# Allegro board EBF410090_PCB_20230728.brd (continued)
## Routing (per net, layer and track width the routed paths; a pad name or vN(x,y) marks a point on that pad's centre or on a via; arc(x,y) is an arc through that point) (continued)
PCIE20_RXN: length 90.5
  TOP w0.179: J24.23 104,70.1 103.79,69.89 103.79,66.76 102.95,65.91 90.05,65.91 89.61,65.47 89.61,57.29 88.65,56.34 68.55,56.34 67.48,57.4 32.56,57.4 32.07,57.89 32.07,60.93 32.01,60.98 J30.187
PCIE20_RXP: length 90.5
  TOP w0.179: J30.185 32.51,60.98 32.45,60.93 32.45,58.05 32.72,57.78 33.58,57.78 arc(33.68,57.82) 33.72,57.92 arc(33.76,58.02) 33.86,58.06 34.3,58.06 arc(34.4,58.02) 34.44,57.92 arc(34.48,57.82) 34.58,57.78 35.01,57.78 arc(35.11,57.82) 35.15,57.92 arc(35.19,58.02) 35.29,58.06 35.72,58.06 arc(35.82,58.02) 35.86,57.92 arc(35.91,57.82) 36,57.78 36.44,57.78 arc(36.54,57.82) 36.58,57.92 arc(36.62,58.02) 36.72,58.06 37.15,58.06 arc(37.25,58.02) 37.29,57.92 arc(37.33,57.82) 37.43,57.78 37.87,57.78 arc(37.97,57.82) 38.01,57.92 arc(38.05,58.02) 38.15,58.06 38.58,58.06 arc(38.68,58.02) 38.72,57.92 arc(38.76,57.82) 38.86,57.78 67.64,57.78 68.71,56.72 88.49,56.72 89.23,57.45 89.23,65.63 89.89,66.29 102.79,66.29 103.41,66.92 103.41,69.89 103.2,70.1 J24.25
PCIE20_TXN: length 72.7
  TOP w0.179: C179.1 v1(88.14,57.48) ; v1(87.34,55.27) 87.04,54.96 81.56,54.96 80.72,55.8 67.92,55.8 67.16,56.56 43.47,56.56 arc(43.37,56.61) 43.33,56.7 arc(43.29,56.8) 43.19,56.84 42.75,56.84 arc(42.65,56.8) 42.61,56.7 arc(42.57,56.61) 42.47,56.56 42.04,56.56 arc(41.94,56.61) 41.9,56.7 arc(41.86,56.8) 41.76,56.84 41.33,56.84 arc(41.23,56.8) 41.19,56.7 arc(41.14,56.61) 41.05,56.56 40.61,56.56 arc(40.51,56.61) 40.47,56.7 arc(40.43,56.8) 40.33,56.84 39.9,56.84 arc(39.8,56.8) 39.76,56.7 arc(39.72,56.61) 39.62,56.56 39.18,56.56 arc(39.08,56.61) 39.04,56.7 arc(39,56.8) 38.9,56.84 38.47,56.84 arc(38.37,56.8) 38.33,56.7 arc(38.29,56.61) 38.19,56.56 37.75,56.56 arc(37.66,56.61) 37.61,56.7 arc(37.57,56.8) 37.47,56.84 37.04,56.84 arc(36.94,56.8) 36.9,56.7 arc(36.86,56.61) 36.76,56.56 36.33,56.56 arc(36.23,56.61) 36.19,56.7 arc(36.14,56.8) 36.05,56.84 35.61,56.84 arc(35.51,56.8) 35.47,56.7 arc(35.43,56.61) 35.33,56.56 34.9,56.56 arc(34.8,56.61) 34.76,56.7 arc(34.72,56.8) 34.62,56.84 34.18,56.84 arc(34.08,56.8) 34.04,56.7 arc(34,56.61) 33.9,56.56 33.47,56.56 arc(33.37,56.61) 33.33,56.7 arc(33.29,56.8) 33.19,56.84 32.75,56.84 arc(32.66,56.8) 32.61,56.7 arc(32.57,56.61) 32.47,56.56 32.08,56.56 31.45,57.19 31.45,60.93 31.51,60.98 J30.189
  BOTTOM w0.179: v1(88.14,57.48) 87.82,57.8 87.82,58.27 88,58.44 88.85,58.44 89.2,58.09 89.2,55.32 88.85,54.96 87.64,54.96 v1(87.34,55.27)
PCIE20_TXP: length 72.7
  TOP w0.179: v1(87.34,54.28) 87.04,54.58 81.4,54.58 80.56,55.42 67.76,55.42 67,56.18 31.92,56.18 31.07,57.03 31.07,60.93 31.01,60.98 J30.191 ; C180.1 v1(87.12,57.48)
  BOTTOM w0.179: v1(87.34,54.28) 87.64,54.58 89.01,54.58 89.59,55.16 89.59,58.25 89.01,58.83 87.84,58.83 87.44,58.42 87.44,57.8 v1(87.12,57.48)
PCIE20_WAKEN_M0: length 113.3
  TOP w0.156: J30.171 v1(36.01,63.75)
  ART03 w0.142: v1(88.17,87.39) 87.69,86.91 86.26,86.91 85.67,87.5 55.24,87.5 54.03,86.28 54.03,75.23 52.83,74.04 52.83,70.89 50.9,68.96 45.69,68.96 42.14,65.4 37.66,65.4 v1(36.01,63.75)
  ART04 w0.142: v1(114.8,72.77) 113.84,73.74 104.52,73.74 104.04,74.22 104.04,85.72 103.4,86.36 89.2,86.36 v1(88.17,87.39)
  BOTTOM w0.156: R209.1 114.62,72.59 v1(114.8,72.77)
PCIE_PWREN_EN: length 86.2
  TOP w0.156: J30.149 v1(41.51,60.78)
  ART03 w0.142: v1(41.51,60.78) 41,60.27 41,59.31 41.2,59.1 44.73,59.1 45.26,58.57 45.26,44.75 48.87,41.15 55.12,41.15 55.37,40.89 57.63,40.89 59.59,42.85 65.28,42.85 66.29,43.86 71.42,43.86 74.93,47.37 87.5,47.37 89.43,49.3 102.59,49.3 v1(103.5,48.39)
  BOTTOM w0.156: v1(103.5,48.39) 103.57,48.32 R206.1
PE_TXN: length 23.6
  TOP w0.179: J24.31 100.8,70.1 100.59,69.9 100.59,68.81 99.98,68.2 89.79,68.2 88.52,66.93 88.52,61.72 87.82,61.02 87.82,59.95 88.14,59.64 C179.2
PE_TXP: length 23.6
  TOP w0.179: C180.2 87.12,59.64 87.44,59.95 87.44,61.18 88.14,61.88 88.14,67.09 89.63,68.58 99.82,68.58 100.21,68.97 100.21,69.9 100,70.1 J24.33
PHY1_LED1: length 86.1
  ART04 w0.203: J14.14 67.27,85.99 66.55,85.27 66.55,76.73 66.88,76.4 66.88,68.15 65.53,66.8 51.89,66.8 50.98,65.89 50.98,54.69 49.78,53.49 49.78,39.5 51.69,37.59 59.94,37.59 61.09,38.73 63.53,38.73 63.73,38.94 63.73,40.36 63.93,40.56 64.76,40.56 v1(65.28,40.04)
  BOTTOM w0.156: R116.1 v1(65.28,40.04) 64.81,40.51 64.39,40.51 63.86,41.04 U16.33
PHY1_LED2: length 103.3
  ART04 w0.203: v1(64.26,40.04) 64.26,38.3 64.06,38.1 62.61,38.1 62.23,37.72 62.23,37.08 61.98,36.83 51.05,36.83 48.84,39.04 48.84,54.3 49.28,54.74 49.28,55.93 49.99,56.64 49.99,66.67 50.88,67.56 64.8,67.56 65.76,68.53 65.76,87.2 66.55,87.98 80.4,87.98 J14.11
  BOTTOM w0.156: U16.34 63.46,40.84 v1(64.26,40.04) R117.1
PHY_CLKOUT125: length 2.8
  TOP w0.156: v1(63.15,40.04) 63.11,40.08 R113.2
  BOTTOM w0.156: U16.35 63.06,40.13 v1(63.15,40.04)
PWM2_M0: length 22.2
  TOP w0.156: J30.159 39.01,63.73 38.61,64.13 36.63,64.13 v1(35.01,65.75)
  ART03 w0.142: v1(35.01,65.75) 34.58,66.18 30.77,66.18 29.11,64.51 v1(25.13,64.51)
  BOTTOM w0.156: v1(25.13,64.51) 25.03,64.41 25.03,60.31 24.8,60.08 R17.1
PWM3_IR: length 141.5
  TOP w0.156: v1(37.51,60.78) 37.51,60.78 J30.165 ; v1(45.42,13.66) 45.42,17.07 42.85,19.63 42.85,50.99 v1(42.26,51.58)
  ART03 w0.142: v1(37.51,60.78) 37.03,60.31 37.03,57.55 37.34,57.25 42.19,57.25 42.69,56.75 42.69,52.01 v1(42.26,51.58) ; v1(127.38,13.21) 126.62,13.97 121.03,13.97 119.25,12.19 85.09,12.19 84.58,12.7 72.52,12.7 70.99,14.22 45.97,14.22 v1(45.42,13.66)
  BOTTOM w0.156: R46.1 C64.1 v1(127.38,13.21)
PWR_3V3_EN: length 84.8
  TOP w0.156: v1(74.68,32.46) 75.06,32.84 75.06,37.72 73.41,39.37 73.41,48.39 71.76,50.03 J30.36
  ART03 w0.142: v1(74.68,32.46) 64.97,32.46 63.7,33.73 28.37,33.73 27.09,35.01 v1(14.98,35.01)
  BOTTOM w0.156: R31.1 v1(14.98,35.01)
PWR_5V_EN: length 63.4
  TOP w0.156: J30.140 45.76,31.17 v1(45.69,31.1)
  ART03 w0.142: v1(15.98,32.95) 16.02,32.99 32.91,32.99 33.2,32.71 33.2,30.33 33.48,30.05 40.36,30.05 41.89,31.58 45.21,31.58 v1(45.69,31.1)
  BOTTOM w0.156: R33.1 14.98,38.74 15.54,38.18 15.54,33.39 v1(15.98,32.95)
PWR_12V_EN: length 47
  TOP w0.156: J30.147 42.01,64.64 v1(42.27,64.9)
  ART03 w0.142: v1(35.86,40.13) 21.81,40.13 v1(21.58,40.36)
  BOTTOM w0.156: v1(35.86,40.13) 35.86,47.22 36.4,47.75 39.17,47.75 39.47,48.06 39.47,57.68 41,59.21 41,61.44 42.27,62.71 v1(42.27,64.9) ; R29.1 v1(21.58,40.36)
PWRON_KEY: length 37.8
  TOP w0.156: J30.235 20.01,63.95 20.32,64.26 20.32,65.01 v1(19.81,65.51) ; SW1.4 SW1.3 2.04,76.26 Z1.2 C60.1 v1(1.27,73.53)
  ART03 w0.142: v1(1.27,73.53) 19.46,73.53 19.79,73.2 19.79,65.54 v1(19.81,65.51)
RECOVERY: length 52.6
  TOP w0.156: R43.2 4.19,55.07 3.86,54.74 1.65,54.74 1.3,54.38 1.3,44.96 1.65,44.6 3.73,44.6 v1(4.69,43.63) ; v1(28.56,43.16) 28.56,50.61 28.26,50.91 J30.202
  ART03 w0.142: v1(28.56,43.16) 28.08,43.64 27.15,43.64 26.7,43.18 8.13,43.18 7.68,43.63 v1(4.69,43.63)
RESET_KEY: length 37.8
  TOP w0.156: SW2.3 SW2.4 2.11,72.64 2.34,72.87 3.41,72.87 Z4.2 C61.1 4.07,74.96 4.39,75.28 v1(4.8,75.28) ; v1(20.81,64.51) 20.81,64.07 20.51,63.77 J30.233
  ART03 w0.142: v1(20.81,64.51) 20.33,64.99 20.33,73.53 19.7,74.17 16.38,74.17 15.27,75.28 v1(4.8,75.28)
RS485_1_A: length 34.2
  TOP w0.254: J10.1 68.33,17.4 66.04,19.68 58.7,19.68 58.04,20.34 58.04,21.46 v1(57.75,21.75)
  BOTTOM w0.156: R71.2 65.05,28.76
  BOTTOM w0.254: v1(57.75,21.75) R80.1 D23.2 56.42,26.04 56.83,26.45 65.1,26.45 65.51,26.86 65.51,27.43 65.05,27.88 U14.6 65.05,28.76
RS485_1_B: length 29.1
  TOP w0.254: v1(58.75,21.75) 58.45,21.45 58.45,20.6 58.95,20.09 66.21,20.09 68.14,18.16 R73.1
  BOTTOM w0.156: R76.1 66.32,28.76
  BOTTOM w0.254: v1(58.75,21.75) R79.1 D21.2 60.23,25.63 60.64,26.03 65.19,26.03 65.2,26.04 65.27,26.04 65.91,26.69 65.91,27.41 66.32,27.82 U14.7 66.32,28.76
RS485_2_A: length 37.2
  TOP w0.254: v1(44.41,21.75) 44.7,21.46 44.7,20.28 45.7,19.28 54.25,19.28 55.91,17.63 58.67,17.63 59.18,17.12 J11.1
  BOTTOM w0.156: R72.2 50.96,28.76
  BOTTOM w0.254: v1(44.41,21.75) R82.1 D24.2 43.08,25.46 43.94,26.32 51,26.32 51.41,26.73 51.41,27.3 50.96,27.76 U15.6 50.96,28.76
RS485_2_B: length 32.7
  TOP w0.254: v1(45.41,21.75) 45.11,21.45 45.11,20.45 45.87,19.68 54.42,19.68 56.07,18.03 59.52,18.03 R74.1
  BOTTOM w0.156: R78.1 52.23,28.76
  BOTTOM w0.254: v1(45.41,21.75) R81.1 D22.2 46.89,25.43 47.37,25.91 51.09,25.91 51.1,25.92 51.17,25.92 51.82,26.56 51.82,27.28 52.23,27.69 U15.7 52.23,28.76
RX8010_NIRQ1: length 165.8
  TOP w0.156: J30.20 75.76,51.11 77.98,48.89 83.16,48.89 83.44,48.61 83.44,43.69 81.31,41.55 81.31,29.49 v1(80.52,28.7)
  ART03 w0.142: v1(80.52,28.7) 76.33,28.7 73.03,25.4 50.16,25.4 49.12,24.36 19.71,24.36 17.37,26.69 2.02,26.69 1.73,26.98 1.73,59.01 2.31,59.59 2.31,62.13 2.72,62.53 2.72,71.65 3.1,72.03 5.61,72.03 v1(6.22,72.64)
  BOTTOM w0.156: v1(6.22,72.64) 7.11,73.53 U12.7
RX8010_NIRQ2: length 168.4
  TOP w0.156: J30.18 76.26,51.3 78.28,49.27 83.31,49.27 83.85,48.74 83.85,43.34 81.92,41.4 81.92,28.93 v1(81.68,28.7)
  ART03 w0.142: v1(81.68,28.7) 81.21,28.22 76.48,28.22 73.2,24.94 50.6,24.94 49.56,23.9 19.52,23.9 17.18,26.24 1.64,26.24 1.3,26.59 1.3,67.51 1.99,68.21 1.99,70.03 v1(1.57,70.46)
  BOTTOM w0.156: v1(1.57,70.46) 1.9,70.79 4.29,70.79 4.7,71.2 4.7,74.29 4.19,74.8 U12.3
RXD1_232: length 23
  ART03 w0.142: v1(20.83,26.41) 21.25,26.84 35.35,26.84 v1(35.84,26.35)
  BOTTOM w0.156: U13.13 36.45,26.96 v1(35.84,26.35)
  BOTTOM w0.254: v1(20.83,26.41) D9.2 R58.1
RXD2_232: length 8.8
  BOTTOM w0.254: U13.8 31.37,25.34 30.93,25.78 28.83,25.78 28.45,25.4 D8.2 R56.1
SARADC_VIN1: length 41.5
  TOP w0.156: v1(4.69,42.63) 5.18,43.12 5.18,43.97 4.19,44.96 R232.2 ; v1(28.56,42.16) 29.06,42.66 29.06,50.82 28.76,51.12 J30.200
  ART03 w0.142: v1(4.69,42.63) 5.12,42.2 10.58,42.2 11.05,42.67 28.05,42.67 v1(28.56,42.16)
SDMMC0_CLK: length 109.6
  TOP w0.156: J30.178 34.26,52.08 v1(33.76,51.58)
  ART03 w0.142: v1(33.76,51.58) 35.66,49.68 35.66,44.63 45.69,34.6 64.13,34.6 64.36,34.37 72.02,34.37 72.19,34.53 72.19,34.84 72.36,35 72.59,35 72.76,34.84 72.76,34.53 72.93,34.37 73.16,34.37 73.33,34.53 73.33,34.84 73.5,35 73.73,35 73.9,34.84 73.9,34.53 74.07,34.37 96.06,34.37 97.2,33.23 113.79,33.23 114.19,32.83 v1(114.19,28.7)
  BOTTOM w0.156: R63.1 113.19,27.56 113.03,27.71 113.03,30.98 113.19,31.14 114.02,31.14 114.19,30.97 v1(114.19,28.7)
SDMMC0_CMD: length 108.4
  TOP w0.156: J30.176 v1(34.76,52.58)
  ART03 w0.142: v1(34.76,52.58) 35.26,53.08 37.99,53.08 38.25,52.83 38.25,51.05 38.79,50.52 38.79,45.01 46.93,36.86 59.37,36.86 60.99,38.48 85.22,38.48 86.99,36.71 109.03,36.71 110.26,35.48 115.72,35.48 116.61,34.59 116.61,25.3 116.33,25.02 v1(115.19,25.02)
  BOTTOM w0.156: R62.1 v1(115.19,25.02)
SDMMC0_D0: length 108.9
  TOP w0.156: J30.174 35.26,52.08 v1(34.76,51.58)
  ART03 w0.142: v1(34.76,51.58) 36.14,50.2 36.14,44.82 45.94,35.03 63.25,35.03 63.55,35.33 63.55,35.89 63.73,36.07 64.16,36.07 64.33,35.9 64.33,35.42 64.49,35.25 64.73,35.25 64.9,35.42 64.9,35.9 65.06,36.07 65.3,36.07 65.47,35.9 65.47,35.42 65.63,35.25 65.87,35.25 66.04,35.42 66.04,35.9 66.2,36.07 75.39,36.07 75.56,35.9 75.56,35.65 75.72,35.48 75.96,35.48 76.13,35.65 76.13,35.9 76.29,36.07 76.6,36.07 76.74,35.92 76.74,35.67 76.91,35.5 77.14,35.5 77.31,35.67 77.31,35.93 77.48,36.09 77.71,36.09 77.88,35.93 77.88,35.67 78.05,35.5 78.28,35.5 78.45,35.67 78.45,35.93 78.62,36.09 78.85,36.09 79.02,35.93 79.02,35.67 79.19,35.5 79.42,35.5 79.59,35.67 79.59,35.93 79.76,36.09 79.99,36.09 80.16,35.93 80.16,35.67 80.33,35.5 80.56,35.5 80.73,35.67 80.73,35.93 80.9,36.09 81.13,36.09 81.3,35.93 81.3,35.67 81.47,35.5 81.7,35.5 81.87,35.67 81.87,35.93 82.04,36.09 82.27,36.09 82.44,35.93 82.44,35.67 82.61,35.5 82.84,35.5 83.01,35.67 83.01,35.93 83.18,36.09 83.41,36.09 83.58,35.93 83.58,35.67 83.75,35.5 83.98,35.5 84.15,35.67 84.15,35.92 84.29,36.07 84.71,36.07 85.95,34.82 96.37,34.82 97.54,33.65 114.15,33.65 114.63,33.17 114.63,28.98 114.91,28.7 v1(115.19,28.7)
  BOTTOM w0.156: R64.1 v1(115.19,28.7)
SDMMC0_D1: length 110.4
  TOP w0.156: J30.172 v1(35.76,52.58)
  ART03 w0.142: v1(115.19,29.84) 115.73,30.38 115.73,33.68 114.78,34.62 104.81,34.62 104.65,34.79 104.65,35.68 104.48,35.84 104.24,35.84 104.08,35.68 104.08,34.79 103.91,34.62 103.67,34.62 103.51,34.79 103.51,35.68 103.34,35.84 103.1,35.84 102.94,35.68 102.94,34.79 102.77,34.62 102.53,34.62 102.37,34.79 102.37,35.68 102.2,35.84 101.96,35.84 101.8,35.68 101.8,34.79 101.63,34.62 101.39,34.62 101.23,34.79 101.23,35.68 101.06,35.84 100.82,35.84 100.66,35.68 100.66,34.79 100.49,34.62 100.25,34.62 100.09,34.79 100.09,35.68 99.92,35.84 99.68,35.84 99.52,35.68 99.52,34.79 99.35,34.62 98.22,34.62 97,35.84 86.28,35.84 85.17,36.96 77.44,36.96 77.28,37.12 77.28,37.3 77.11,37.46 76.87,37.46 76.71,37.3 76.71,37.12 76.54,36.96 76.3,36.96 76.14,37.12 76.14,37.3 75.97,37.46 75.73,37.46 75.57,37.3 75.57,37.12 75.4,36.96 62.87,36.96 61.9,36 46.42,36 37.27,45.14 37.27,51.84 37,52.11 36.99,52.11 36.24,52.11 v1(35.76,52.58)
  BOTTOM w0.156: R65.1 v1(115.19,29.84)
SDMMC0_D2: length 108.9
  TOP w0.156: J30.170 36.26,52.08 v1(35.76,51.58)
  ART03 w0.142: v1(114.19,23.87) 113.67,24.4 113.67,32.41 113.33,32.74 96.8,32.74 95.61,33.93 64.11,33.93 63.87,34.17 45.41,34.17 35.12,44.46 35.12,49.21 33.12,51.21 33.12,51.81 33.41,52.09 35.25,52.09 v1(35.76,51.58)
  BOTTOM w0.156: R60.1 114.45,22.73 114.19,23 v1(114.19,23.87)
SDMMC0_D3: length 109.8
  TOP w0.156: J30.168 v1(36.76,52.58)
  ART03 w0.142: v1(36.76,52.58) 37.13,52.58 37.69,52.02 37.69,45.32 46.59,36.42 61.57,36.42 63.04,37.89 85.02,37.89 86.64,36.27 105.18,36.27 105.36,36.09 105.36,35.3 105.6,35.05 107.08,35.05 107.25,35.22 107.25,35.85 107.41,36.02 107.65,36.02 107.82,35.85 107.82,35.22 107.98,35.05 108.22,35.05 108.39,35.22 108.39,35.85 108.55,36.02 108.79,36.02 108.96,35.85 108.96,35.22 109.12,35.05 115.32,35.05 116.15,34.21 116.15,26.09 115.87,25.81 114.82,25.81 114.58,25.56 114.58,24.48 v1(115.19,23.87)
  BOTTOM w0.156: R61.1 v1(115.19,23.87)
SDMMC0_DET_L: length 96.5
  TOP w0.156: v1(36.76,51.58) 37.26,52.08 J30.166
  ART03 w0.142: v1(115.19,30.99) 115.19,33.35 114.43,34.11 97.97,34.11 96.72,35.36 86.1,35.36 84.93,36.53 63.35,36.53 62.34,35.51 46.17,35.51 36.76,44.92 v1(36.76,51.58)
  BOTTOM w0.156: R66.1 v1(115.19,30.99)
SIM_CLK0: length 34.7
  TOP w0.156: v1(116.12,35.99) 116.12,35.47 115.77,35.13 112.78,35.13 112.47,35.44 112.47,43.41 109.78,46.1 109.78,59.05 111.6,60.88 J24.12
  BOTTOM w0.156: v1(116.12,35.99) 115.95,35.82 R202.1
SIM_DATA0: length 29.9
  TOP w0.156: v1(113.12,35.99) 113.12,44.08 110.31,46.89 110.31,58.93 112.4,61.02 J24.10
  BOTTOM w0.156: v1(113.12,35.99) 112.9,35.78 R204.1
SIM_RST0: length 33.4
  TOP w0.156: v1(111.73,37.16) 111.76,37.18 111.76,43.1 109.27,45.59 109.27,59.28 110.8,60.81 J24.14
  BOTTOM w0.156: v1(111.73,37.16) 111.73,32.75 112.35,32.13 R201.1
SIM_VDD: length 51.5
  TOP w0.305: J24.8 113.2,60.98 111,58.77 111,47.4 114.12,44.27 v1(114.12,35.99)
  ART04 w0.381: v1(119.37,31.72) 119.37,33.13 118.67,33.83 114.73,33.83 114.12,34.44 v1(114.12,35.99)
  BOTTOM w0.305: v1(114.12,35.99) 113.92,35.79 R200.1 ; v1(119.37,31.72) 119.37,31.72 U38.1 119.96,32.37 120.27,32.68 120.27,34.92 119.15,36.04 119.15,39.67 119.74,40.26 U37.1
SPKN_OUT: length 35.4
  TOP w0.254: J30.236 19.76,57.22 v1(20.32,57.78)
  BOTTOM w0.156: 30.49,69.98 R224.1
  BOTTOM w0.254: 30.49,69.98 Z13.2 30.2,68.67 30.2,64.05 31.57,62.68 31.57,54.92 29.79,53.14 24.16,53.14 22.78,54.52 22.78,57.23 21.95,58.06 20.6,58.06 v1(20.32,57.78)
SPKP_OUT: length 36
  TOP w0.254: v1(20.32,58.78) 19.26,57.72 J30.238
  BOTTOM w0.156: 29.46,69.98 R223.1
  BOTTOM w0.254: 29.46,69.98 Z11.2 29.79,68.62 29.79,63.88 31.14,62.53 31.14,55.07 29.62,53.54 24.33,53.54 23.19,54.69 23.19,57.39 22.12,58.47 20.63,58.47 v1(20.32,58.78)
SS_TXN: length 8.7
  BOTTOM w0.158: J15.8 96.29,78.87 96.45,79.03 96.45,79.31 95.82,79.94 95.82,83.84 95.75,83.91 U19.2 U19.9 95.75,86.32 C114.1
SS_TXP: length 9.5
  BOTTOM w0.158: C115.1 96.25,86.22 U19.10 U19.1 96.25,83.91 96.18,83.84 96.18,83.56 arc(96.23,83.44) 96.35,83.39 arc(96.47,83.34) 96.52,83.22 96.52,82.92 arc(96.47,82.8) 96.35,82.75 arc(96.23,82.7) 96.18,82.58 96.18,82.29 arc(96.23,82.17) 96.35,82.12 arc(96.47,82.07) 96.52,81.95 96.52,81.66 arc(96.47,81.54) 96.35,81.49 arc(96.23,81.44) 96.18,81.32 96.18,80.09 96.81,79.46 96.81,79.08 97.02,78.87 J15.9
TXD1_232: length 34.6
  ART03 w0.142: v1(18.83,26.41) 19.41,25.83 37.32,25.83 v1(37.84,26.35)
  BOTTOM w0.156: v1(37.84,26.35) 37.71,26.48 U13.14
  BOTTOM w0.254: R59.1 D11.2 10.79,25.91 11.3,26.41 v1(18.83,26.41)
TXD2_232: length 16.3
  BOTTOM w0.254: R57.1 D10.2 24.64,26.67 25.02,27.05 32,27.05 32.63,26.42 U13.7
UART1_DIR: length 73.6
  TOP w0.156: v1(35.91,19.94) 36.33,20.35 36.33,30.32 32.76,33.89 J30.184
  ART03 w0.142: v1(35.91,19.94) 36.57,19.28 37.49,19.28 38.35,20.14 63.84,20.14 v1(65.41,21.71)
  BOTTOM w0.156: U14.3 65.05,24.93 65.37,25.24 66.01,25.24 66.32,24.93 U14.2 R75.1 v1(65.41,21.71)
UART1_RX_M0: length 82.4
  TOP w0.156: J30.194 30.26,20.27 30.39,20.14 30.39,19.42 v1(29.91,18.94)
  ART03 w0.142: v1(29.91,18.94) 29.36,19.48 29.36,22.83 30,23.47 66.75,23.47 v1(68.51,21.71)
  BOTTOM w0.156: U14.1 R69.2 v1(68.51,21.71)
UART1_TX_M0: length 73.3
  TOP w0.156: J30.196 29.76,20.09 v1(29.91,19.94)
  ART03 w0.142: v1(29.91,19.94) 29.91,22.49 30.53,23.11 61.46,23.11 v1(62.87,21.71)
  BOTTOM w0.156: v1(62.87,21.71) R67.2 U14.4
UART2_RX_M0_DEBUG: length 63.6
  TOP w0.156: v1(39.76,35.16) 40.31,35.71 40.31,50.37 39.76,50.92 J30.156
  ART03 w0.142: v1(39.76,35.16) 39.28,35.64 27.86,35.64 27.61,35.89 18.54,35.89 18.16,35.51 5.19,35.51 4.69,35.01 v1(4.69,34.01)
  BOTTOM w0.156: U10.4 4.1,29.35 3.95,29.5 R42.2 3.95,33.26 v1(4.69,34.01)
UART2_TX_M0_DEBUG: length 78.7
  TOP w0.156: v1(8.25,20.69) 7.21,21.73 7.21,35.75 6.8,36.17 5.35,36.17 v1(4.69,36.82) ; J30.158 39.26,50.65 39.76,50.15 v1(39.76,36.16)
  ART03 w0.142: v1(4.69,36.82) 5.3,36.22 15.67,36.22 16.33,36.87 39.04,36.87 v1(39.76,36.16)
  BOTTOM w0.156: v1(8.25,20.69) U9.2 5.37,20.69 5.08,20.4 5.08,18.95 5.37,18.66 R39.2
UART3_RX_M1: length 71.7
  TOP w0.156: v1(72.56,29.56) 71.37,30.75 71.37,33.65 70.46,34.57 70.46,37.82 68.45,39.83 68.45,44.32 67.76,45.01 J30.52
  ART03 w0.142: v1(31.37,30.61) 31.37,29.27 31.66,28.99 71.99,28.99 v1(72.56,29.56)
  BOTTOM w0.156: R52.2 31.37,31.37 v1(31.37,30.61) U13.9
UART3_TX_M1: length 68.3
  TOP w0.156: v1(71.56,29.56) 70.1,31.02 70.1,33.4 69.47,34.03 69.47,37.84 67.94,39.37 67.94,43.81 67.26,44.5 J30.54
  ART03 w0.142: v1(32.63,30.61) 32.63,30 33.08,29.56 v1(71.56,29.56)
  BOTTOM w0.156: U13.10 v1(32.63,30.61) 32.64,30.61 R53.2
UART4_RX_M1: length 66.4
  TOP w0.156: J30.48 68.76,45.92 69.47,45.21 69.47,40.64 72.56,37.55 v1(72.56,31.56)
  ART03 w0.142: v1(72.56,31.56) 72.4,31.39 63.14,31.39 62.61,31.93 51.66,31.93 50.79,32.8 35.62,32.8 35.17,32.35 v1(35.17,30.61)
  BOTTOM w0.156: R54.2 35.18,30.61 v1(35.17,30.61) U13.12
UART4_TX_M1: length 71.8
  TOP w0.156: J30.50 68.26,45.4 68.96,44.7 68.96,40.26 72.01,37.21 72.01,31.14 72.37,30.78 73.25,30.78 73.56,31.09 v1(73.56,31.56)
  ART03 w0.142: v1(73.56,31.56) 73.08,32.04 64.51,32.04 64.02,32.52 51.9,32.52 51.16,33.27 34.42,33.27 33.91,32.77 v1(33.91,30.61)
  BOTTOM w0.156: R55.2 33.91,30.61 v1(33.91,30.61) U13.11
UART6_DIR: length 57.9
  TOP w0.156: v1(36.91,19.94) 37.34,20.37 37.34,30.42 33.26,34.5 J30.182
  ART03 w0.142: v1(36.91,19.94) 38.13,21.16 50.81,21.16 v1(51.36,21.71)
  BOTTOM w0.156: U15.3 50.96,24.8 51.27,25.11 51.92,25.11 52.23,24.8 U15.2 R77.1 v1(51.36,21.71)
UART6_RX_M0: length 62.3
  TOP w0.156: J30.190 31.26,32.19 31.95,31.49 31.95,19.98 v1(31.91,19.94)
  ART03 w0.142: v1(54.36,21.71) 53.42,22.66 32.56,22.66 31.91,22 v1(31.91,19.94)
  BOTTOM w0.156: U15.1 R70.2 v1(54.36,21.71)
UART6_TX_M0: length 57.6
  TOP w0.156: v1(30.91,19.94) 30.76,20.09 J30.192
  ART03 w0.142: v1(48.82,21.71) 48.33,22.2 32.87,22.2 32.41,21.74 32.41,19.69 32.13,19.4 31.44,19.4 v1(30.91,19.94)
  BOTTOM w0.156: v1(48.82,21.71) R68.2 U15.4
UART7_RX_M0: length 109.3
  TOP w0.156: R225.2 v1(99.19,19.18) ; J30.186 32.26,33.27 34.47,31.06 34.47,20.38 v1(34.91,19.94)
  ART03 w0.142: v1(34.91,19.94) 35.43,19.41 35.43,18.57 35.72,18.29 82.77,18.29 83.06,18.57 83.06,22.6 83.44,22.99 98.55,22.99 99.19,22.35 v1(99.19,19.18)
UART7_TX_M0: length 109.1
  TOP w0.156: R234.2 v1(97.16,19.18) ; v1(32.91,19.94) 33.27,20.3 33.27,31.06 31.76,32.58 J30.188
  ART03 w0.142: v1(97.16,19.18) 97.16,22.19 96.87,22.48 83.91,22.48 83.63,22.19 83.63,18.1 83.31,17.78 33.91,17.78 33.4,18.29 33.4,19.45 v1(32.91,19.94)
UART9_RX_M1: length 93.4
  TOP w0.156: J30.98 56.26,50.73 55.75,50.22 55.75,34.54 56.51,33.79 56.51,29.22 57.11,28.62 70.82,28.62 74.3,25.14 74.3,18.79 75.44,17.65 v1(75.44,14.48)
  ART03 w0.142: v1(111.12,16.89) 109.41,15.18 83.51,15.18 83.19,14.86 75.82,14.86 v1(75.44,14.48)
  BOTTOM w0.156: R235.2 v1(111.12,16.89)
UART9_TX_M1: length 92.7
  TOP w0.156: v1(74.3,14.48) 74.3,17.78 73.79,18.29 73.79,25.02 70.87,27.94 56.64,27.94 56.01,28.57 56.01,33.53 55.12,34.42 55.12,50.29 55.76,50.93 J30.100
  ART03 w0.142: v1(74.3,14.48) 75.12,15.3 83,15.3 83.32,15.62 107.82,15.62 v1(109.09,16.89)
  BOTTOM w0.156: R236.2 v1(109.09,16.89)
USB2_HOST2_DM: length 43.5
  TOP w0.158: R126.1 v1(93.47,32.38) ; v1(79.01,60.78) 79.01,60.78 J30.7
  BOTTOM w0.158: v1(79.01,60.78) 79.33,60.46 83.78,60.46 84.48,59.77 84.48,58.22 86.28,56.41 86.28,53.42 87,52.7 91.19,52.7 92.39,51.5 92.39,35.66 arc(92.44,35.55) 92.55,35.5 arc(92.66,35.46) 92.71,35.34 92.71,35.03 arc(92.66,34.92) 92.55,34.87 arc(92.44,34.82) 92.39,34.71 92.39,34.4 arc(92.44,34.28) 92.55,34.24 arc(92.75,34.15) 92.84,33.95 92.84,33.89 arc(92.75,33.69) 92.55,33.6 arc(92.44,33.56) 92.39,33.44 92.39,32.37 92.72,32.05 93.15,32.05 93.47,32.37 v1(93.47,32.38)
USB2_HOST2_DP: length 43.8
  TOP w0.158: R125.1 v1(93.47,31.37) ; J30.9 78.51,60.28 v1(79.01,59.78)
  BOTTOM w0.158: v1(79.01,59.78) 79.33,60.1 83.63,60.1 84.12,59.62 84.12,58.07 85.92,56.26 85.92,53.27 86.85,52.34 91.04,52.34 92.03,51.35 92.03,32.22 92.57,31.68 93.16,31.68 v1(93.47,31.37)
USB2_HOST3_DM: length 84.4
  TOP w0.158: v1(99.54,88.38) 99.84,88.08 99.84,87.1 103.02,83.92 103.02,75.84 101.58,74.4 88.75,74.4 87.78,73.42 87.78,70.25 86.89,69.36 86.89,65.17 85.4,63.68 81.71,63.68 81.17,63.14 81.17,61.19 79.27,59.29 78.26,59.29 77.94,59.6 77.94,60.95 78.01,61.02 J30.11 ; R143.2 v1(126.49,88.39)
  ART03 w0.144: v1(99.54,88.38) 99.85,88.07 99.85,87.24 100.34,86.75 102.38,86.75 102.99,87.36 108.26,87.36 108.8,86.82 118.05,86.82 118.69,87.46 125.71,87.46 126.06,87.81 126.06,87.96 v1(126.49,88.39)
USB2_HOST3_DP: length 84.4
  TOP w0.158: R142.2 v1(125.48,88.39) ; v1(100.5,88.38) 100.2,88.08 100.2,87.25 103.38,84.07 103.38,75.69 101.73,74.04 88.9,74.04 88.14,73.27 88.14,70.1 87.25,69.21 87.25,65.02 85.55,63.32 81.86,63.32 81.53,62.99 81.53,61.04 79.42,58.93 78.11,58.93 77.58,59.46 77.58,60.95 77.51,61.02 J30.13
  ART03 w0.144: v1(125.48,88.39) 125.71,88.15 125.71,87.95 125.57,87.81 118.54,87.81 117.91,87.17 108.94,87.17 108.41,87.71 102.84,87.71 102.23,87.1 100.48,87.1 100.2,87.38 100.2,88.07 v1(100.5,88.38)
USB3_HOST1_DM: length 38.9
  TOP w0.158: J30.3 80.01,63.52 79.94,63.59 79.94,63.99 80.6,64.64 84.81,64.64 86,65.84 86,74.8 84.96,75.84 84.96,76.93 85.32,77.29 85.32,78.23 86.76,79.67 87.85,79.67 89.53,81.35 89.53,82.37 91.41,84.25 93.98,84.25 94.72,84.99 94.72,86.74 94.35,87.11 94.35,88.1 v1(94.64,88.39)
  BOTTOM w0.158: R136.2 v1(94.64,88.39)
USB3_HOST1_DP: length 38.9
  TOP w0.158: v1(93.7,88.39) 93.99,88.1 93.99,86.96 94.36,86.59 94.36,85.14 93.83,84.61 91.26,84.61 89.17,82.52 89.17,81.5 87.7,80.03 86.61,80.03 84.96,78.38 84.96,77.44 84.6,77.08 84.6,75.69 85.64,74.65 85.64,65.99 84.66,65 80.45,65 79.58,64.14 79.58,63.59 79.51,63.52 J30.5
  BOTTOM w0.158: R137.2 v1(93.7,88.39)
USB3_HOST1_SSRXN: length 99
  TOP w0.158: v1(29.01,59.78) 28.51,60.28 J30.201
  ART03 w0.144: v1(29.01,59.78) 28.69,60.11 28.13,60.11 27.64,60.6 27.64,62.35 28.36,63.06 37.93,63.06 39.02,64.15 42.33,64.15 46.14,67.97 63.68,67.97 65.9,70.2 83.9,70.2 84.79,71.08 84.79,84.71 85.74,85.67 91.98,85.67 92.27,85.95 92.27,86.51 v1(91.96,86.82)
  BOTTOM w0.158: J15.5 90.13,78.87 90.45,79.19 90.45,79.65 91.44,80.64 91.44,82.42 92.26,83.25 92.26,83.84 92.19,83.91 U18.2 U18.9 92.19,85.76 92.26,85.83 92.26,86.52 v1(91.96,86.82)
USB3_HOST1_SSRXP: length 97.3
  TOP w0.158: J30.199 v1(29.01,60.78)
  ART03 w0.144: v1(29.01,60.78) 28.69,60.46 28.28,60.46 27.99,60.74 27.99,62.2 28.5,62.71 38.07,62.71 39.17,63.8 42.47,63.8 46.29,67.62 63.82,67.62 66.05,69.85 84.05,69.85 85.13,70.93 85.13,84.56 85.89,85.32 92.13,85.32 92.62,85.81 92.62,86.51 v1(92.93,86.82)
  BOTTOM w0.158: v1(92.93,86.82) 92.62,86.52 92.62,85.83 92.69,85.76 U18.10 U18.1 92.69,83.91 92.62,83.84 92.62,83.1 91.8,82.27 91.8,80.49 90.81,79.5 90.81,79.19 91.13,78.87 J15.6
USB3_HOST1_SSTXN: length 91
  TOP w0.158: J30.197 29.51,60.28 v1(30.01,59.78)
  ART03 w0.144: v1(95.58,88.39) 95.72,88.25 95.72,86.88 94.18,85.34 94.18,82.68 93.47,81.96 91.66,81.96 90.91,81.21 90.91,79.73 90.51,79.33 90.51,78.4 90.91,78.01 90.91,76.53 90.41,76.03 90.41,75.28 89.9,74.77 86.67,74.77 85.78,73.87 85.78,70.59 84.38,69.19 69.36,69.19 68.92,68.75 66.4,68.75 64.58,66.92 46.59,66.92 42.82,63.14 39.77,63.14 38.82,62.19 29.88,62.19 29.53,61.85 29.53,60.18 29.93,59.78 v1(30.01,59.78)
  BOTTOM w0.158: C114.2 v1(95.58,88.39)
USB3_HOST1_SSTXP: length 90.3
  TOP w0.158: J30.195 v1(30.01,60.78)
  ART03 w0.144: v1(96.52,88.39) 96.22,88.39 96.07,88.25 96.07,86.74 94.53,85.2 94.53,82.53 93.62,81.62 91.8,81.62 91.25,81.07 91.25,79.59 90.86,79.19 90.86,78.55 91.25,78.15 91.25,76.39 90.75,75.89 90.75,75.13 90.04,74.42 86.82,74.42 86.12,73.73 86.12,70.44 84.52,68.84 69.5,68.84 69.06,68.4 66.55,68.4 64.72,66.57 46.74,66.57 42.96,62.8 39.91,62.8 38.96,61.85 34.78,61.85 arc(34.67,61.8) 34.63,61.7 arc(34.58,61.59) 34.48,61.54 34.21,61.54 arc(34.1,61.59) 34.05,61.7 arc(34.01,61.8) 33.9,61.85 33.63,61.85 arc(33.52,61.8) 33.48,61.7 arc(33.43,61.59) 33.33,61.54 33.06,61.54 arc(32.95,61.59) 32.9,61.7 arc(32.86,61.8) 32.75,61.85 32.48,61.85 arc(32.37,61.8) 32.33,61.7 arc(32.28,61.59) 32.18,61.54 31.91,61.54 arc(31.8,61.59) 31.75,61.7 arc(31.71,61.8) 31.6,61.85 31.33,61.85 arc(31.22,61.8) 31.18,61.7 arc(31.13,61.59) 31.03,61.54 30.76,61.54 arc(30.65,61.59) 30.6,61.7 arc(30.56,61.8) 30.45,61.85 30.02,61.85 29.88,61.7 29.88,60.91 v1(30.01,60.78)
  BOTTOM w0.158: C115.2 v1(96.52,88.39)
USB20_HOST_PWR_EN: length 115.2
  TOP w0.156: J30.28 73.76,50.32 75.69,48.39 75.69,44.32 76.67,43.35 v1(77.24,43.35)
  ART03 w0.142: v1(77.24,43.35) 77.76,43.86 78.66,43.86 79.68,44.88 87.81,44.88 89.61,46.68 114.17,46.68 115.95,48.46 v1(117.83,48.46)
  ART04 w0.142: v1(134.44,71.38) 134.2,71.14 127.46,71.14 127.18,70.86 127.18,61.19 126.89,60.91 126.09,60.91 125.81,60.62 125.81,51.61 124.54,50.34 122.58,50.34 121.26,49.02 118.39,49.02 v1(117.83,48.46)
  BOTTOM w0.156: v1(134.44,71.38) 135.13,72.07 135.13,79.09 134.75,79.48 131.88,79.48 131.52,79.83 131.52,81.36 131.24,81.63 130.06,81.63 129.74,81.95 129.74,83.1 129.43,83.41 128.99,83.41 128.7,83.7 128.7,85.42 128.4,85.72 R141.1
USB20_OTG_PWR_EN: length 56.1
  TOP w0.156: J30.138 v1(46.26,52.58)
  ART03 w0.142: v1(45.59,72.47) 21.82,72.47 21.46,72.11 21.46,66.17 v1(20.81,65.51)
  BOTTOM w0.156: v1(45.59,72.47) 45.57,72.44 45.57,66.9 46.26,66.21 v1(46.26,52.58) ; v1(20.81,65.51) 20.32,65.02 20.32,63.88 19.94,63.5 R150.1
USB30_HOST_PWR_EN: length 62.1
  TOP w0.156: J30.41 70.51,60.78
  TOP w0.305: 70.51,60.78 v1(70.51,60.78)
  BOTTOM w0.156: v1(70.51,60.78) 70.51,61.95 70.92,62.36 73.51,62.36 73.94,62.79 73.94,65.91 74.45,66.42 84.52,66.42 84.84,66.73 84.84,70.99 85.34,71.5 90.55,71.5 93.6,74.55 102.68,74.55 103.12,74.99 103.12,83.38 103.44,83.69 109.6,83.69 110.11,84.2 R147.1
USB OTG: length 55.3
  TOP w0.305: R149.1 v1(38.35,46.57)
  ART03 w0.305: v1(44.08,75.36) 38.81,75.36 37.08,77.09 32.38,77.09 30.17,79.3 v1(24.13,79.3)
  BOTTOM w0.305: v1(38.35,46.57) 41.24,46.57 41.68,47.01 41.68,56.72 44.32,59.36 44.32,75.12 v1(44.08,75.36)
  vias: v1(23.13,80.3) v1(23.13,79.3) v1(24.13,80.3)
USB_OTG0_DM: length 39.3
  TOP w0.158: J30.203 28.01,63.52 27.94,63.59 27.94,64 28.1,64.15 28.73,64.15 29.36,63.52 31.72,63.52 32.64,64.44 32.64,65.33 35.06,67.75 35.06,86.25 34.57,86.74 29.56,86.74 28.1,88.21 28.1,88.58 v1(28.45,88.94)
  BOTTOM w0.158: v1(28.45,88.94) 28.45,88.28 R134.2
USB_OTG0_DP: length 41.9
  TOP w0.158: J30.205 27.51,63.52 27.58,63.59 27.58,64.15 27.95,64.51 28.88,64.51 29.51,63.89 31.57,63.89 32.28,64.59 32.28,65.48 34.7,67.9 34.7,76.65 arc(34.65,76.77) 34.53,76.82 arc(34.41,76.87) 34.37,76.98 34.37,77.29 arc(34.41,77.4) 34.53,77.45 arc(34.65,77.5) 34.7,77.62 34.7,77.92 arc(34.65,78.04) 34.53,78.09 arc(34.41,78.13) 34.37,78.25 34.37,78.55 arc(34.41,78.67) 34.53,78.72 arc(34.65,78.77) 34.7,78.88 34.7,79.19 arc(34.65,79.3) 34.53,79.35 arc(34.41,79.4) 34.37,79.52 34.37,79.82 arc(34.41,79.94) 34.53,79.98 arc(34.65,80.03) 34.7,80.15 34.7,80.45 arc(34.65,80.57) 34.53,80.62 arc(34.41,80.67) 34.37,80.78 34.37,81.09 arc(34.41,81.2) 34.53,81.25 arc(34.65,81.3) 34.7,81.42 34.7,81.72 arc(34.65,81.83) 34.53,81.88 arc(34.41,81.93) 34.37,82.05 34.37,82.35 arc(34.41,82.47) 34.53,82.52 arc(34.65,82.56) 34.7,82.68 34.7,82.98 arc(34.65,83.1) 34.53,83.15 arc(34.41,83.2) 34.37,83.31 34.37,83.62 arc(34.41,83.73) 34.53,83.78 arc(34.65,83.83) 34.7,83.95 34.7,84.25 arc(34.65,84.37) 34.53,84.42 arc(34.41,84.46) 34.37,84.58 34.37,84.88 arc(34.41,85) 34.53,85.05 arc(34.65,85.1) 34.7,85.21 34.7,86.1 34.42,86.38 29.41,86.38 27.73,88.06 27.73,88.63 v1(27.43,88.94)
  BOTTOM w0.158: v1(27.43,88.94) 27.43,88.28 R135.2
USB_OTG0_ID: length 44.1
  TOP w0.156: J30.160 v1(38.76,52.58)
  ART03 w0.142: v1(43.08,76.38) 38.94,76.38 37.34,77.98 33.16,77.98 v1(31.52,79.62)
  BOTTOM w0.156: v1(43.08,76.38) 42.55,75.84 42.55,67.16 41.75,66.36 41.75,62.96 40.01,61.21 40.01,59.18 38.76,57.94 v1(38.76,52.58) ; v1(31.52,79.62) 31.13,80.01 R138.2
USB_OTG0_VBUSDET: length 6.3
  TOP w0.156: R149.2 38.91,48.81 38.91,50.11 R151.1 38.26,50.76 J30.162
USER_LED: length 123.1
  TOP w0.156: v1(44.69,31.1) 45.26,31.67 J30.142 ; v1(128.65,16.12) 128.65,18.59 128.33,18.91 R45.2
  ART03 w0.142: v1(44.69,31.1) 45.21,30.58 84.04,30.58 85.38,29.23 109.96,29.23 110.44,28.75 110.44,21.89 110.87,21.46 119.38,21.46 120.8,20.04 120.8,16.95 121.64,16.12 v1(128.65,16.12)
WLAN_PWR_EN: length 92.3
  TOP w0.156: R128.1 91.94,29.67 91.63,29.35 89.95,29.35 88.9,30.4 v1(88.9,49.5)
  TOP w0.179: v1(41.51,59.78) 41.01,60.28 J30.151
  ART03 w0.142: v1(41.51,59.78) 45.44,59.78 45.72,59.5 45.72,45.44 48.92,42.24 55.24,42.24 55.68,41.81 57.08,41.81 59.29,44.02 64.6,44.02 65.35,44.78 71.45,44.78 74.55,47.88 87.28,47.88 v1(88.9,49.5)
N03801: length 3.8
  BOTTOM w0.203: C8.2 R4.2 R6.1 6.17,55.81 U3.4
N15118698: length 3.7
  BOTTOM w0.156: U1.4 C4.1 R1.2
N15119063: length 1.9
  BOTTOM w0.156: R2.1 7.93,33.84 U1.3
N15122947: length 3.4
  BOTTOM w0.156: U2.4 17.34,53.79 C9.1 R3.2
N15123057: length 2
  BOTTOM w0.156: U2.3 17.34,49.01 17.14,48.82 R5.1
N15599533: length 3.3
  BOTTOM w0.156: U16.25 67.65,44.65 R96.2
N15599537: length 3.5
  BOTTOM w0.156: U16.24 67.03,45.05 R97.2
N15599541: length 4
  BOTTOM w0.156: R99.2 67.56,46.6 67.56,46.23 66.79,45.45 U16.23
N15599545: length 4.5
  BOTTOM w0.156: U16.22 66.55,45.85 67.06,46.35 67.06,46.73 67.56,47.24 67.56,47.62 R100.2
N15599549: length 3.2
  BOTTOM w0.156: R101.2 67.79,43.85 U16.27
N15599553: length 3
  BOTTOM w0.156: U16.26 68.26,44.25 R102.2
N15599792: length 7.5
  BOTTOM w0.305: R90.2 R94.1 R93.1 R91.1 73.41,43.57 73.15,43.31 R95.1
N15600759: length 3.1
  BOTTOM w0.156: R108.1 R109.1 64.26,51.55 R107.1 R106.2
N15600826: length 6.9
  BOTTOM w0.156: U16.31 64.67,41.4 64.8,41.27 65.35,41.27 66.55,40.08 R110.2 67.18,38.47 67.18,37.33 R112.2
N15601838: length 6.6
  BOTTOM w0.156: U16.37 62.27,39.78 C83.1 62.23,38.47 62.23,37.33 Y1.1
N15601846: length 8.1
  BOTTOM w0.156: U16.36 62.67,39.69 C84.1 62.54,38.4 62.54,35.78 Y1.3
N15602572: length 6.5
  BOTTOM w0.156: R118.1 65.91,37.33 65.91,40.13 65.15,40.89 64.59,40.89 64.27,41.22 U16.32
N15602600: length 2.2
  TOP w0.156: R121.2 v1(64.26,37.43) R122.1
  BOTTOM w0.156: R117.2 v1(64.26,37.43)
N15603170: length 4
  BOTTOM w0.508: C85.1 J14.1
N15605512: length 3.2
  BOTTOM w0.156: U16.39 61.46,40.94 61.4,40.87 61.4,40.86 61.21,40.68 61.21,39.74 R98.1
N15605755: length 11.7
  BOTTOM w0.203: U16.28 67.02,43.45
  BOTTOM w0.305: R89.1 R92.1 C79.1 C80.1 73.41,42.24 72.98,42.67 67.8,42.67 67.02,43.45
N15611443: length 3.4
  BOTTOM w0.156: U21.4 C118.1 R141.2
N15611553: length 1.8
  BOTTOM w0.156: R144.1 118.69,87.56 U21.3
N15653247: length 5.7
  BOTTOM w0.203: R150.2 C124.1 16.58,64.51 16.38,64.71 16.38,66.67 16.58,66.87 U25.4
N15653357: length 2.5
  BOTTOM w0.156: U25.3 18.86,66.87 18.67,66.67 18.67,65.9 R153.1
N15653957: length 3.6
  BOTTOM w0.156: U24.4 108.78,87.56 109.09,87.25 C121.1 R147.2
N15654067: length 4.2
  BOTTOM w0.156: U24.3 103.83,87.56 103.5,87.88 103.5,88.52 103.76,88.77 R148.1
N15659726: length 3.7
  TOP w0.203: R7.2 R8.1 C18.2 5.21,54.99 v1(5.33,54.86)
  BOTTOM w0.203: U3.5 v1(5.33,54.86)
N15752445: length 38.1
  TOP w0.762: U26.G3 U26.G4
  ART03 w0.762: U26.G2 58.09,84.8 59.01,85.72 63.67,85.72 64.59,84.8 U26.G4
  BOTTOM w0.762: U26.G2 58.09,70.1 ; U26.G4 64.64,82.26 L9.1
N15772454: length 3
  TOP w0.156: R162.2 128.27,49.02 128.77,48.53 J19.14
N15774097: length 12.7
  TOP w0.156: J18.14 132.65,70.62 133.55,69.72 v1(133.55,68.24)
  BOTTOM w0.156: v1(133.55,68.24) 133.03,67.73 131.99,67.73 131.83,67.56 131.83,65.28 131.32,64.77 R161.2
N15830872: length 26.6
  TOP w0.203: C190.2 v1(28.45,71.13)
  BOTTOM w0.203: v1(28.45,71.13) 28.08,71.5 Z9.2 28.08,73.27 27.07,74.28 27.07,76.4 28.01,77.34 33.93,77.34 34.22,77.34 35.18,78.3 35.18,81.61 35.79,82.22 36.83,82.22 37.24,81.81 J25.5 37.44,80.57 J25.3
N15830941: length 32.1
  TOP w0.203: C189.2 v1(26.45,71.13)
  BOTTOM w0.203: v1(26.45,71.13) 26.79,71.47 Z8.2 26.79,73.16 26.26,73.69 26.26,76.7 27.61,78.05 33.93,78.05 34.47,78.59 34.47,81.98 35.73,83.23 38.2,83.23 J25.2 43.12,84.27 R218.2
N15838979: length 6.8
  BOTTOM w0.254: R217.2 33.53,73.91 34.29,74.67 J25.4
N15851038: length 2
  TOP w0.254: R216.1 37.22,65.66 C185.1 R215.2
N15852295: length 5.5
  BOTTOM w0.254: R223.2 29.82,71.34 29.82,74.95 28.97,75.8 J29.1
N15852481: length 5.1
  BOTTOM w0.254: J29.2 30.23,75.26 30.23,71.24 R224.2
N15980269: length 2.3
  TOP w0.254: J10.2 70.52,16.34 R73.2
N16735828: length 1.9
  TOP w0.156: R45.1 LED1.1
N16735933: length 1.9
  TOP w0.156: R48.1 LED2.1
N16793147: length 6.2
  BOTTOM w0.156: J9.1 119.97,22.26 D12.2 118.91,22.15 117.54,22.15 R60.2
N16793149: length 6.1
  BOTTOM w0.156: J9.7 119.66,28.86 D16.2 118.91,28.12 117.54,28.12 R64.2
N16793151: length 6.4
  BOTTOM w0.156: R63.2 117.52,27 118.94,27 D15.2 120.4,26.66 J9.5
N16793153: length 6.2
  BOTTOM w0.156: R62.2 117.54,24.43 118.91,24.43 D14.2 120.06,24.46 J9.3
N16793155: length 6.2
  BOTTOM w0.156: J9.2 120.01,23.36 D13.2 118.94,23.32 117.52,23.32 R61.2
N16793157: length 6
  BOTTOM w0.156: J9.8 119.61,29.96 D17.2 118.94,29.29 117.52,29.29 R65.2
N16793300: length 6
  BOTTOM w0.156: J9.9 119.57,31.06 D18.2 118.94,30.43 117.52,30.43 R66.2
N16795570: length 1.9
  TOP w0.156: R49.1 LED3.1
N16795883: length 6.8
  TOP w0.156: R25.1 3.17,67.94 v1(3.43,68.2)
  TOP w0.203: R24.2 C37.2 R25.1 R23.2
  BOTTOM w0.203: U5.5 v1(3.43,68.2)
N16811933: length 3.9
  TOP w0.156: J24.1 v1(116,69.4)
  BOTTOM w0.156: v1(116,69.4) 116,69.87 R208.2 R209.2
N16823854: length 2.7
  TOP w0.156: J24.7 v1(113.6,69.4)
  BOTTOM w0.156: R210.2 v1(113.6,69.4)
N16928945: length 3.9
  TOP w0.156: R211.1 105.2,59.25 J24.20
N16929135: length 4
  TOP w0.156: R212.1 104.4,59.31 J24.22
N16980859: length 18.9
  BOTTOM w0.156: U37.2 121.58,42.8 121.26,42.49 121.26,41.13 120.95,40.82 119.3,40.82 118.67,40.18 118.67,35.76 119.37,35.06 U38.6 119.37,33.14 119.13,32.89 116.72,32.89 C178.1 R201.2
N16980861: length 18.2
  BOTTOM w0.156: R202.2 C177.1 117.54,33.72 U38.4 118.37,33.72 118.37,34.79 117.65,35.51 117.65,40.82 118.67,41.83 120.04,41.83 120.32,42.11 120.32,44.59 120.63,44.9 121.05,44.9 121.49,45.34 U37.3
N16980863: length 21.2
  BOTTOM w0.156: R204.2 R200.2 C176.1 114.94,33.53 115.26,33.2 116.14,33.2 118.65,33.2 118.87,33.42 U38.5 118.87,34.92 118.14,35.66 118.14,40.54 118.95,41.35 120.41,41.35 120.73,41.66 120.73,43.46 121.34,44.07 U37.7
N17405290: length 3.8
  BOTTOM w0.203: U5.4 2.48,68.91 R22.1 R20.2 C29.2
N17423608: length 5.9
  TOP w0.203: R14.2 R15.1 C27.2 11.94,54.61 v1(12.19,54.86)
  BOTTOM w0.203: U4.5 v1(12.19,54.86)
N17423737: length 3.9
  BOTTOM w0.203: C20.2 R11.2 R13.1 13.15,55.81 U4.4
N17430242: length 1.8
  BOTTOM w0.156: U7.3 7.8,41.59 R34.1
N17430314: length 3.8
  BOTTOM w0.156: R33.2 C47.1 U7.4
N17443353: length 1.9
  BOTTOM w0.156: R32.1 8.23,37.84 8.42,37.65 U6.3
N17443371: length 3.7
  BOTTOM w0.156: R31.2 C41.1 U6.4
N17444423: length 16.7
  BOTTOM w0.156: 20.57,43.04 R27.2
  BOTTOM w0.203: 20.57,43.04 20.57,42.42 20.34,42.19 17.36,42.19 17.11,41.93 Q6.3 ; R27.2 C38.2 20.01,45.02 Q4.1 18.57,45.59 14.61,45.59 13.98,44.96 11.96,44.96 Q5.1
N17444523: length 3.3
  BOTTOM w0.156: R29.2 R30.1 Q6.1
N17454508: length 7
  BOTTOM w0.156: U13.1 40.25,20 39.94,19.68 38.03,19.68 37.72,20 C71.2
N17454513: length 1.8
  BOTTOM w0.156: U13.3 37.72,23.49 C71.1
N17455367: length 1.8
  BOTTOM w0.156: C72.2 36.45,23.49 U13.4
N17455372: length 3.9
  BOTTOM w0.156: C72.1 35.49,20.71 35.17,21.02 U13.5
N17455499: length 1.8
  BOTTOM w0.156: C70.1 33.91,21.71 U13.6
N17455508: length 1.8
  BOTTOM w0.156: C68.1 U13.2
N17466585: length 0.9
  BOTTOM w0.203: U16.30 65.94,42.65 66.17,42.42
N17592172: length 3.9
  BOTTOM w0.156: U36.4 R205.1 R203.2 C169.2
N17592286: length 3.6
  BOTTOM w0.156: R206.2 103.57,46.08 103.36,45.87 101.85,45.87 101.47,45.49 U36.5
N17633217: length 6.1
  TOP w0.156: U22.3 124.59,77.74 C119.1 124.71,77.08 124.71,75.71 Y2.1
N17633237: length 4.3
  TOP w0.156: U22.4 125.09,77.74 C120.2 125.36,76.82 Y2.3
N17633305: length 2.3
  TOP w0.156: U22.16 124.59,86.36 R145.2
N17633317: length 2.3
  TOP w0.156: R146.2 123.59,86.35 U22.18
N17685591: length 13.1
  TOP w0.203: Q12.1 122.82,34.73 123.06,34.49 123.06,32.49 122.14,31.56 Q13.1 122.96,30.68 122.96,27.68 123.22,27.43 Q14.3 125.35,27.43 125.6,27.68 C165.2 R196.2
N17685601: length 3.1
  TOP w0.156: Q14.1 122.02,28.45 R199.1 R198.2
N17690217: length 1.3
  BOTTOM w0.156: U35.3 69.66,23.81 R195.1
N17690290: length 4.9
  BOTTOM w0.156: R193.2 C162.1 69.66,31.31 U35.4
N17695706: length 11.5
  TOP w0.156: C139.1 120.96,65.28 120.42,64.74 120.42,63.9 120.76,63.56 v1(120.83,63.56) U29.4 ; v1(120.83,67.49) 120.83,68.07 121.15,68.39 U31.4
  BOTTOM w0.156: v1(120.83,67.49) 120.35,67 120.35,65.07 120.77,64.65 120.77,63.63 ; 120.77,63.63 v1(120.83,63.56) ; 120.77,63.63 R172.2
N17695791: length 3.2
  TOP w0.156: U31.3 125.21,68.39 125.5,68.1 125.5,66.98 125.68,66.8 R175.1
N17695827: length 2
  TOP w0.156: U29.3 125.36,63.56 125.53,63.73 R174.1
N17697466: length 3.9
  BOTTOM w0.508: R114.1 74.68,85.99 J14.13
N17697880: length 2
  TOP w0.156: U33.3 125.31,60.26 125.48,60.43 R182.1
N17697953: length 4.3
  TOP w0.156: R180.2 C150.1 U33.4
N17701231: length 2.4
  TOP w0.254: J11.2 61.72,17.29 61.38,17.63 R74.2
N17702194: length 9
  BOTTOM w0.254: R81.2 45.57,20.15 45.13,19.72 45.13,18.93 44.42,18.22 42.99,18.22 42.42,17.65 42.42,16.38 42.67,16.13 J12.3
N17702199: length 9
  BOTTOM w0.254: R82.2 44.32,20.15 44.72,19.75 44.72,19.1 44.25,18.63 42.82,18.63 42.01,17.82 42.01,16.36 41.79,16.13 J12.4
N17702222: length 14.4
  BOTTOM w0.254: R80.2 57.49,20.15 58,19.65 58,18.98 57.49,18.47 50.28,18.47 49.63,17.82 49.63,16.64 49.13,16.13 J12.2
N17702231: length 14.6
  BOTTOM w0.254: J12.1 50.54,16.13 50.04,16.64 50.04,17.65 50.45,18.06 57.66,18.06 58.41,18.81 58.41,19.65 58.92,20.15 R79.2
N17728858: length 1.4
  BOTTOM w0.305: D19.1 64.31,32.59 64.52,32.38 R71.1
N17729021: length 1.4
  BOTTOM w0.305: D20.1 50.22,32.59 50.43,32.38 R72.1
N17731599: length 4.7
  BOTTOM w0.254: J8.6 10.79,17.83 R59.2
N17731608: length 4.3
  BOTTOM w0.254: R58.2 20.83,16.85 J8.4
N17731627: length 5.3
  BOTTOM w0.254: R56.2 28.45,19.22 J8.1
N17748815: length 1.8
  BOTTOM w0.508: R26.2 13.61,43.12 Q5.2
N17750545: length 2.7
  BOTTOM w0.156: Q1.1 24.32,65.98 R12.2 23.37,65.03 Q2.3
N17750554: length 8.3
  BOTTOM w0.381: Q1.3 23.37,70.43 23.67,70.74 D2.1 24.13,71.67 J2.1
N17750632: length 2.9
  BOTTOM w0.156: R18.1 R17.2 24.32,61.14 Q2.1
N17770939: length 2.7
  TOP w0.158: R142.1 125.8,86.17 125.8,86.05 125.18,85.44 125.18,85.11 125.09,85.02 U22.15
N17770942: length 2.6
  TOP w0.158: R143.1 126.16,86.17 126.16,85.9 125.55,85.29 125.55,85.06 125.59,85.02 U22.14
N17861933: length 4.1
  TOP w0.381: U11.2 v1(124.22,10.29)
  BOTTOM w0.381: v1(124.22,10.29) 123.82,10.69 C65.1 C66.1 R47.1
N17863087: length 2.9
  TOP w0.156: U11.3 v1(125.49,10.29)
  BOTTOM w0.156: v1(125.49,10.29) 125.48,10.29 R44.2 R46.2
N17946485: length 9.6
  TOP w0.156: SW3.4 1.43,62.59 1.12,62.29 1.12,58.6 1.43,58.29 SW3.3 2.16,58.24 Z5.2 C63.1 R43.1
N17975561: length 8.6
  BOTTOM w0.305: J7.1 16.87,76.85 16.38,77.34 D7.2 12.69,76.33 R51.1 R50.2
N18056005: length 3.5
  TOP w0.156: R128.2 R127.2 C109.2 90.94,33.24 Q7.1
N18056634: length 11.7
  TOP w0.156: U17.2 106.28,29.34 arc(105.21,28.89) 104.77,27.82 C107.1 104.78,23.74
  TOP w0.508: C106.1 104.78,23.74
N18056637: length 2.7
  TOP w0.156: 104.78,20.69 C108.1 104.78,20.71
  TOP w0.508: CN1.1 104.78,20.69 ; C106.2 104.78,20.71
N18057325: length 4.4
  TOP w0.158: U17.7 97.9,32.37 97.58,32.06 96.03,32.06 95.7,32.38 R126.2
N18057335: length 4.1
  TOP w0.158: U17.6 97.9,31.54 97.74,31.7 96.03,31.7 95.7,31.37 R125.2
N18091011: length 1.4
  BOTTOM w0.156: D6.1 11.68,74.57 R50.1
N18111918: length 18.4
  TOP w0.156: v1(123.04,46.05) 122.8,46.29 U32.4 120.86,46.29 120.68,46.47 120.68,47.7 120.86,47.88 R171.2 ; U30.4 120.81,41.46 120.57,41.69 120.57,42.54 120.95,42.92 C136.1 123.12,42.37 124.75,42.37 v1(125.31,42.92)
  BOTTOM w0.156: v1(123.04,46.05) 124.79,46.05 125.31,45.53 v1(125.31,42.92)
N18111989: length 3.1
  TOP w0.156: R176.1 125.71,44.7 125.4,45.02 125.4,46.07 125.19,46.29 U32.3
N18112037: length 2
  TOP w0.156: U30.3 125.21,41.46 125.37,41.63 R173.1
N18115454: length 2
  TOP w0.156: R188.1 125.48,38.33 125.31,38.16 U34.3
N18115527: length 4.5
  TOP w0.156: U34.4 C153.1 R187.2
N18173560: length 25.9
  TOP w0.508: L8.1 21.08,83.7 21.59,84.21 J16.C4
  ART03 w0.508: J16.C4 23.01,86.38 23.5,86.87 31.16,86.87 31.65,86.38 J16.C3
  BOTTOM w0.508: J16.C3 J16.C1 ; J16.C4 J16.C2
N18175084: length 1.7
  BOTTOM w0.156: D26.3 27.05,80.51 R138.1
N18245213: length 26.4
  TOP w0.156: LED4.1 7.93,49.27 8.11,49.09 9.85,49.09 10.16,49.4 10.16,52.01 10.47,52.32 v1(12.26,52.32)
  ART03 w0.142: v1(12.26,52.32) 11.25,53.34 6.48,53.34 6.15,53.67 6.15,63.72 v1(6.21,63.78)
  BOTTOM w0.156: v1(6.21,63.78) 6.73,63.25 Q3.3
N18245628: length 1.5
  TOP w0.156: R16.2 LED4.2
N18246356: length 2.4
  BOTTOM w0.156: R19.2 R21.1 7.23,59.66 Q3.1
N18288623: length 8.8
  TOP w0.156: R239.1 R232.1 C192.1 Z23.2 2.09,47.94 SW4.3 SW4.4
N18341998: length 3.8
  BOTTOM w0.508: R111.1 76.96,85.99 J14.12
N18348384: length 4.3
  BOTTOM w0.254: J8.3 24.64,16.85 R57.2
N18461230: length 3.9
  BOTTOM w0.156: Q4.2 19.08,43.05
  BOTTOM w0.508: 19.08,43.05 R26.1
N18494968: length 9.7
  TOP w0.156: J34.2 90.01,12.36 D48.2 85.96,16.41 85.96,17.89 R237.1
N18494970: length 10
  TOP w0.156: R238.1 87.23,17.89 87.23,16.41 D47.2 92.01,11.63 J34.3
N18495009: length 6.5
  TOP w0.156: J32.2 78.35,11.01 D50.2 R222.1
N18495011: length 6.6
  TOP w0.156: R233.1 D49.2 79.38,11.3 J32.3
N18495097: length 9.2
  TOP w0.156: J35.2 102.01,13.44 D52.2 R234.1
N18495099: length 9.2
  TOP w0.156: J35.3 104.01,13.47 D51.2 R225.1
N18495175: length 8.9
  BOTTOM w0.156: R236.1 D54.2 110.11,14.03 110.42,13.71 113.57,13.71 114.01,13.28 J36.2
N18495177: length 9.1
  BOTTOM w0.156: R235.1 D53.2 112.14,14.61 112.15,14.6 115.57,14.6 116.01,14.16 J36.3

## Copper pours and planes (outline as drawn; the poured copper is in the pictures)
1V05_PHY on BOTTOM: 67.64,38.81 71.35,38.81 71.48,38.94 71.48,41.99 71.3,42.16 70.13,42.16 70.13,39.78 69.95,39.6 67.79,39.6 67.64,39.45
3V3_AVDD_PHY on BOTTOM: 57.73,40.31 59.72,40.31 59.87,40.16 59.87,38.81 58.93,38.81 58.72,38.61 58.72,38.33 57.91,38.33 57.91,39.45 57.73,39.62
3V3_EDP on TOP: 131.37,25.55 131.44,25.37 131.62,25.3 132.64,25.3 132.82,25.37 132.89,25.55 132.89,25.83 132.82,26.01 132.64,26.08 131.62,26.08 131.44,26.01 131.37,25.83
3V3_EDP on BOTTOM: 71.25,25.91 71.25,24.38 73.28,24.38 73.53,24.13 73.53,17.14 73.66,17.02 74.93,17.02 75.06,17.14 75.06,25.78 74.8,26.03 71.37,26.03
3V3_EDP on ART04: 130.66,25.96 132.72,25.96 133.12,25.55 133.12,15.09 132.26,14.22 79.15,14.22 78.64,13.71 78.64,11.4 78.33,11.1 57.78,11.1 57.43,11.45 57.43,17.14 57.89,17.6 129.41,17.6 130.25,18.44 130.25,25.55
3V3_IMAGE_1 on TOP: 130.63,65.48 125.15,65.48 124.43,66.19 123.72,66.19 123.72,66.8 125.2,66.8 125.73,66.27 130.63,66.27
3V3_IMAGE_2 on TOP: 130.63,43.36 124.03,43.36 123.72,43.66 123.72,44.7 124.92,44.7 124.92,44.22 125.12,44.02 129.18,44.02 129.34,44.17 130.63,44.17
5V0_CAM_1 on BOTTOM: 131.06,68.81 131.06,67.46 130.89,67.28 127.81,67.28 127.64,67.46 127.64,68.66 127.81,68.83 131.04,68.83
5V0_CAM_1 on ART03: 128.98,58.34 126.11,58.34 125.83,58.62 125.83,67.41 126.29,67.87 129.03,67.87 129.21,67.69 129.21,67.08 129.03,66.9 127.46,66.9 127.15,66.6 127.15,59.71 127.41,59.46 128.98,59.46 129.21,59.23 129.21,58.57
5V0_CAM_2 on TOP: 123.65,36.04 123.72,35.86 123.9,35.79 128.93,35.79 129.11,35.86 129.18,36.04 129.18,36.4 129.11,36.58 128.93,36.65 123.9,36.65 123.72,36.58 123.65,36.4
5V0_CAM_2 on BOTTOM: 129.79,52.04 129.79,37.46 129.39,37.06 127.86,37.06 127.61,36.8 127.61,36.12 127.86,35.86 130.4,35.86 131.09,36.55 131.09,52.04
5V0_IMAGE_1 on TOP: 130.63,65.28 130.63,61.57 130.33,61.26 123.8,61.26 123.7,61.37 123.7,61.97 125.81,61.97 125.88,62.05 129.01,62.05 129.34,62.38 129.34,65.28
5V0_IMAGE_2 on TOP: 130.66,43.18 130.66,39.45 130.33,39.11 123.83,39.11 123.7,39.24 123.7,39.85 125.81,39.85 125.91,39.95 129.03,39.95 129.34,40.26 129.34,43.18
12V_EDP on TOP: 123.47,30.15 127.76,30.15 127.99,30.38 127.99,33.91 127.81,34.09 127.03,34.09 126.85,33.91 126.85,31.49 126.44,31.09 123.47,31.09
GND on TOP (solid shape): 84.57,79.25 84.68,79.21 84.73,79.1 84.73,78.04 83.48,78.01 83.51,79.25
GND on BOTTOM (solid shape): 26.96,30.69 26.29,30.03 26.16,30 26.04,30.03 25.36,30.69 26.16,31.56
GND on TOP: 65.56,53.31 65.63,53.13 65.81,53.06 66.75,53.06 66.93,53.13 67.01,53.31 67.01,55.7 66.93,55.88 66.75,55.96 65.81,55.96 65.63,55.88 65.56,55.7
GND on TOP: 111.89,48.26 111.35,48.79 111.35,58.24 111.53,58.42 118.67,58.42 118.67,59.84 118.74,60.02 118.92,60.1 122.68,60.1 122.68,68.43 122.99,68.73 130.07,68.73 130.81,67.99 130.81,58.27 130.45,57.91 129.26,57.91 129.26,58.75 128.07,58.75 128.07,57.91 123.62,57.91 123.62,57.3 123.55,57.12 123.37,57.05 120.68,57.05 120.68,49.25 119.68,48.26 ; 7 cut-outs
GND on TOP: 55.37,61.29 55.19,61.36 55.12,61.54 55.12,65.78 55.24,65.91 57.28,65.91 57.4,65.78 57.4,64.85 58.57,64.85 59.46,63.96 59.46,63.93 59.51,63.88 69.7,63.88 70.64,64.82 78.08,64.82 78.99,65.73 80.31,65.73 80.52,65.53 80.52,64.57 79.25,63.3 78.74,63.3 78.74,63.37 77.83,63.37 77.83,63.42 76.71,63.42 76.71,63.37 76.58,63.37 76.58,63.3 67.87,63.3 67.87,61.54 67.79,61.36 67.61,61.29
GND on TOP: 7.75,55.88 7.75,54.35 7.87,54.23 8.51,54.23 8.64,54.35 8.64,55.88 8.51,56.01 7.87,56.01
GND on TOP: 60.63,47.09 62.89,47.09 63.14,46.84 63.14,43.36 62.89,43.1 60.66,43.1 60.63,43.13
GND on TOP: 60.55,53.29 60.63,53.11 60.81,53.03 62.2,53.03 62.38,53.11 62.46,53.29 62.46,55.68 62.38,55.86 62.2,55.93 60.81,55.93 60.63,55.86 60.55,55.68
GND on TOP: 30.18,79.15 30.25,78.97 30.43,78.89 33.1,78.89 33.28,78.97 33.35,79.15 33.35,83.11 33.27,83.18 32.26,83.18 31.5,83.95 30.35,83.95 30.18,83.77
GND on TOP: 14.94,51.12 14.94,52.5 15.11,52.68 15.11,60.76 15.37,61.01 15.37,63.5 15.24,63.63 14.73,63.63 14.61,63.75 14.61,64.13 14.73,64.26 16.51,64.26 16.66,64.11 16.66,60.27 16.43,60.04 16.43,51.1 16.38,51.05 15,51.05
GND on TOP: outline of 91 points within 0.51,8.51 136.49,89.49 ; 5 cut-outs
GND on TOP: 122.99,31.24 126.24,31.24 126.77,31.77 126.77,34.62 127.3,35.15 129.74,35.15 130.63,36.04 130.63,43.92 130.84,44.12 131.78,44.12 132.03,44.37 132.03,45.8 131.9,45.92 123.32,45.92 122.45,45.06 122.45,31.77
GND on TOP: 9.98,72.13 10.36,71.75 10.36,69.26 9.7,68.6 9.7,65.35 8,65.35 7.85,65.51 7.85,66.42 7.47,66.8 3.96,66.8 3.91,66.85 3.91,71.96 4.09,72.13
GND on TOP: 15.34,70.26 15.42,70.08 15.6,70 17.65,70 17.83,70.08 17.91,70.26 17.91,72.97 17.83,73.15 17.65,73.23 15.6,73.23 15.42,73.15 15.34,72.97
GND on TOP: 65.71,46.15 65.71,36.57 65.56,36.42 63.07,36.42 62.74,36.75 62.74,42.26 63.65,43.18 63.65,46.51 63.83,46.68 65.18,46.68
GND on TOP: 93.22,33.27 93.29,33.09 93.47,33.02 95.5,33.02 95.68,33.09 95.76,33.27 95.76,34.42 95.68,34.6 95.5,34.67 93.47,34.67 93.29,34.6 93.22,34.42
GND on TOP: 4.9,48.44 4.9,53.87 5.11,54.08 6.38,54.08 6.6,53.85 6.6,47.62 6.48,47.5 5.97,47.5 5.84,47.62 5.84,48.26 5.71,48.39 4.95,48.39
GND on TOP: 102.23,30.61 102.23,16.89 102.64,16.48 107.01,16.48 107.44,16.92 107.44,25.78 107.82,26.16 112.52,26.16 112.9,26.54 112.9,31.11 102.74,31.11 ; 1 cut-out
GND on TOP: 64.26,64.9 64.34,64.72 64.52,64.64 68.2,64.64 68.38,64.72 68.45,64.9 68.45,66.17 68.38,66.35 68.2,66.42 64.52,66.42 64.34,66.35 64.26,66.17
GND on TOP: 8.26,47.62 8.26,45.72 8.38,45.59 9.65,45.59 9.78,45.72 9.78,47.5 9.65,47.62
GND on TOP: 125.6,28.4 125.68,28.22 125.86,28.14 128.78,28.14 128.96,28.22 129.03,28.4 129.03,29.74 128.96,29.92 128.78,30 125.86,30 125.68,29.92 125.6,29.74
GND on BOTTOM: 14.68,46.58 14.68,52.37 14.94,52.63 16.31,52.63 16.54,52.4 16.54,46.68 16.43,46.58
GND on BOTTOM: 121.49,31.7 121.56,31.52 121.74,31.44 125.45,31.44 125.63,31.52 125.7,31.7 125.7,34.82 125.63,35 125.45,35.08 121.74,35.08 121.56,35 121.49,34.82
